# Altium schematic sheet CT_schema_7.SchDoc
size 274 x 160 mm
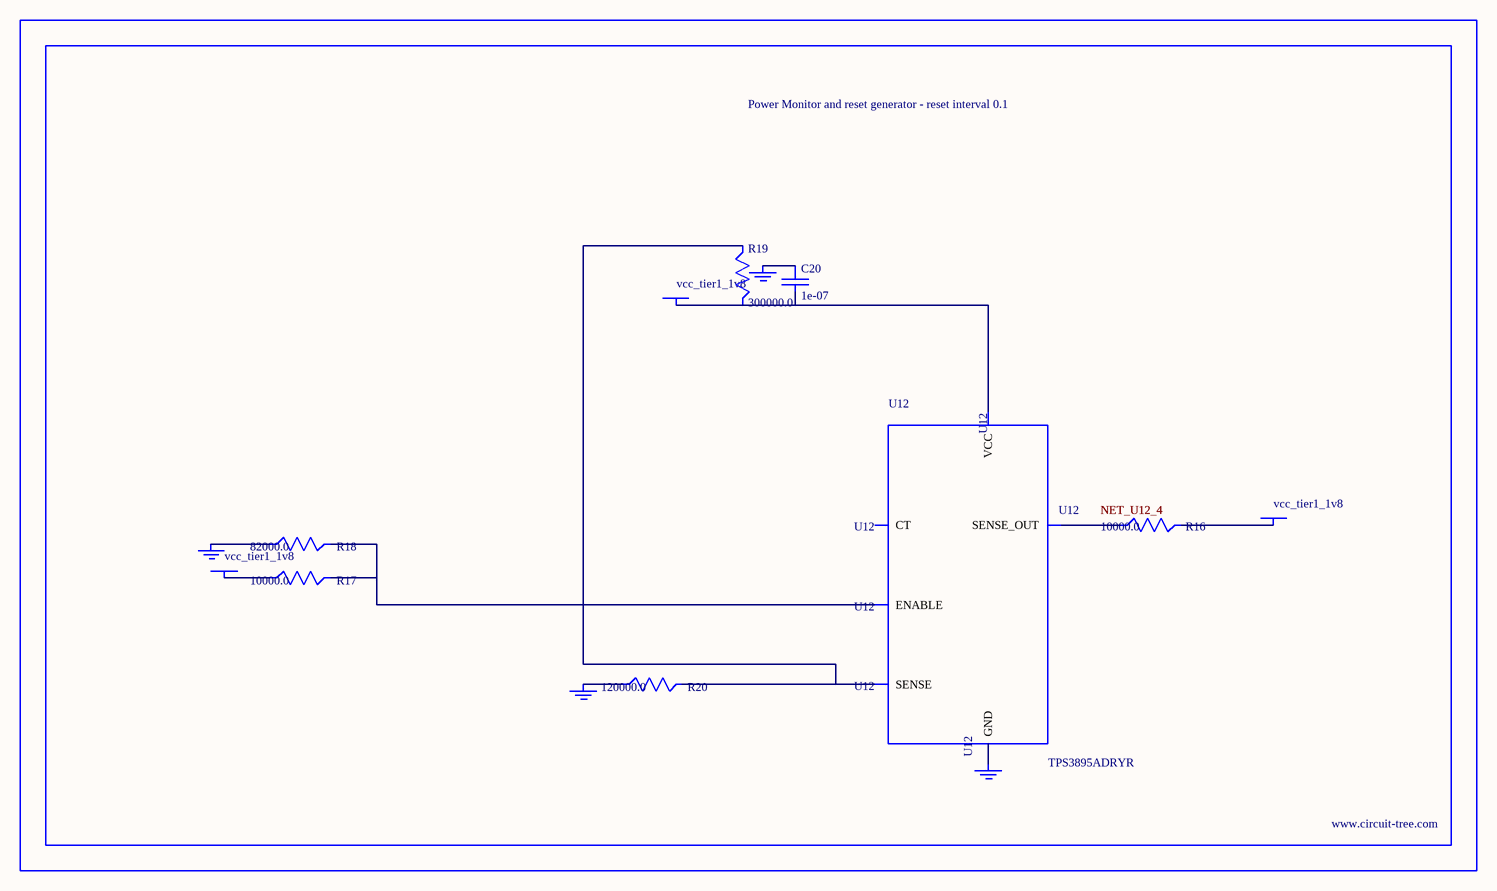
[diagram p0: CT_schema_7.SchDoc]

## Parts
BORDER6  (no value)
C20  1e-07  [C0402]
GND_INSTANCE_6_0  (no value)
GND_INSTANCE_6_1  (no value)
GND_INSTANCE_6_2  (no value)
GND_INSTANCE_6_3  (no value)
POWER_INSTANCE_6_0  vcc_tier1_1v8
POWER_INSTANCE_6_1  vcc_tier1_1v8
POWER_INSTANCE_6_2  vcc_tier1_1v8
R16  10000.0  [R0603]
R17  10000.0  [R0603]
R18  82000.0  [R0603]
R19  300000.0  [R0603]
R20  120000.0  [R0603]
U12  TPS3895ADRYR  [SON-6]

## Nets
NetC20_1: C20.1 GND_INSTANCE_6_2.0(GND)
NetC20_2: C20.2 POWER_INSTANCE_6_2.0(PWR) R19.2 U12.6(VCC)
NetGND_INSTANCE_6_0_0: GND_INSTANCE_6_0.0(GND) R18.1
NetGND_INSTANCE_6_1_0: GND_INSTANCE_6_1.0(GND) R20.1
NetGND_INSTANCE_6_3_0: GND_INSTANCE_6_3.0(GND) U12.2(GND)
NetPOWER_INSTANCE_6_0_0: POWER_INSTANCE_6_0.0(PWR) R17.1
NetPOWER_INSTANCE_6_1_0: POWER_INSTANCE_6_1.0(PWR) R16.2
NetR16_1: R16.1 U12.4(SENSE_OUT)
NetR17_2: R17.2 R18.2 U12.1(ENABLE)
NetR19_1: R19.1 R20.2 U12.3(SENSE)

Not connected (* = marked no-connect by the designer): U12 5(CT)

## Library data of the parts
BORDER6 = BORDER_PAGE6
C20 = C0402C104K3RACTU
GND_INSTANCE_6_0-GND_INSTANCE_6_3 = GND
POWER_INSTANCE_6_0-POWER_INSTANCE_6_2 = PWR
R16 R17 = RC0603JR-0710KL
R18 = RC0603JR-0782KL
R19 = RC0603JR-07300KL
R20 = RC0603JR-07120KL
